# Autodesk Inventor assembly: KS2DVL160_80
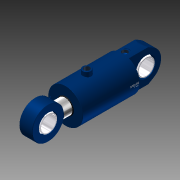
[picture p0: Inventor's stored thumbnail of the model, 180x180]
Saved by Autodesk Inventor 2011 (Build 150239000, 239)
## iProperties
Created: 2010-11
Document SubType Name: Assembly
Designer: TB
Mass: 566.294 g
Surface Area: 1153.75 cm^2
Volume: 566.294 cm^3
Density: 1 g/cm^3
Description: KS2DVL 160/80 - 100 mm
Slaglengde: 100,000 mm
Author: TB
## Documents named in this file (6)
- C:\Vault\Sylinderteknikk\Projects_ST\3D.nettkatalog\KS2-Series\KS2DVL\KS2DVL160_80\KS2DVL160_80.iam
- C:\Vault\Sylinderteknikk\Projects_ST\3D.nettkatalog\KS2-Series\KS2DVL\KS2DVL160_80\KS2DVL160_80_stang.ipt
- C:\Vault\Sylinderteknikk\Projects_ST\3D.nettkatalog\KS2-Series\KS2DVL\KS2DVL160_80\KS2DVL160_80_Parameters.ipt
- C:\Vault\Sylinderteknikk\Projects_ST\3D.nettkatalog\KS2-Series\KS2DVL\KS2DVL160_80\KS2DVL160_80_body..ipt
- C:\Vault\Sylinderteknikk\Projects_ST\Øyer\Klinkby.KS.Øyer\KS.80.eye.komplett\Kule80HO.ipt
- C:\Vault\Sylinderteknikk\Projects_ST\Øyer\Klinkby.KS.Øyer\KS.80.eye.komplett\KS.80.eye.komplett.1.ipt
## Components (5 placed, 5 different names)
1. KS2DVL160_80_Parameters:3
2. KS2DVL160_80_stang:1 — Mate:1, FriMate:2, Mate:3, Insert:3
3. KS2DVL160_80_body.:1 — Mate:1, FriMate:2, Mate:3, Insert:2, Angle:1
4. Kule80HO:1 — Insert:2
5. KS.80.eye.komplett.1:1 — Insert:3, Angle:1
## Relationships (6: Mate 3, Insert 2, Angle 1)
- Mate:1: KS2DVL160_80_stang:1 ↔ KS2DVL160_80_body.:1
- FriMate:2 [Mate]: KS2DVL160_80_stang:1 ↔ KS2DVL160_80_body.:1
- Mate:3: KS2DVL160_80_stang:1 ↔ KS2DVL160_80_body.:1
- Insert:2: KS2DVL160_80_body.:1 ↔ Kule80HO:1
- Insert:3: KS2DVL160_80_stang:1 ↔ KS.80.eye.komplett.1:1
- Angle:1: KS2DVL160_80_body.:1 ↔ KS.80.eye.komplett.1:1
## Named parameters: Forlengelse_rør = 0, Vinkel_Minusport = 0
